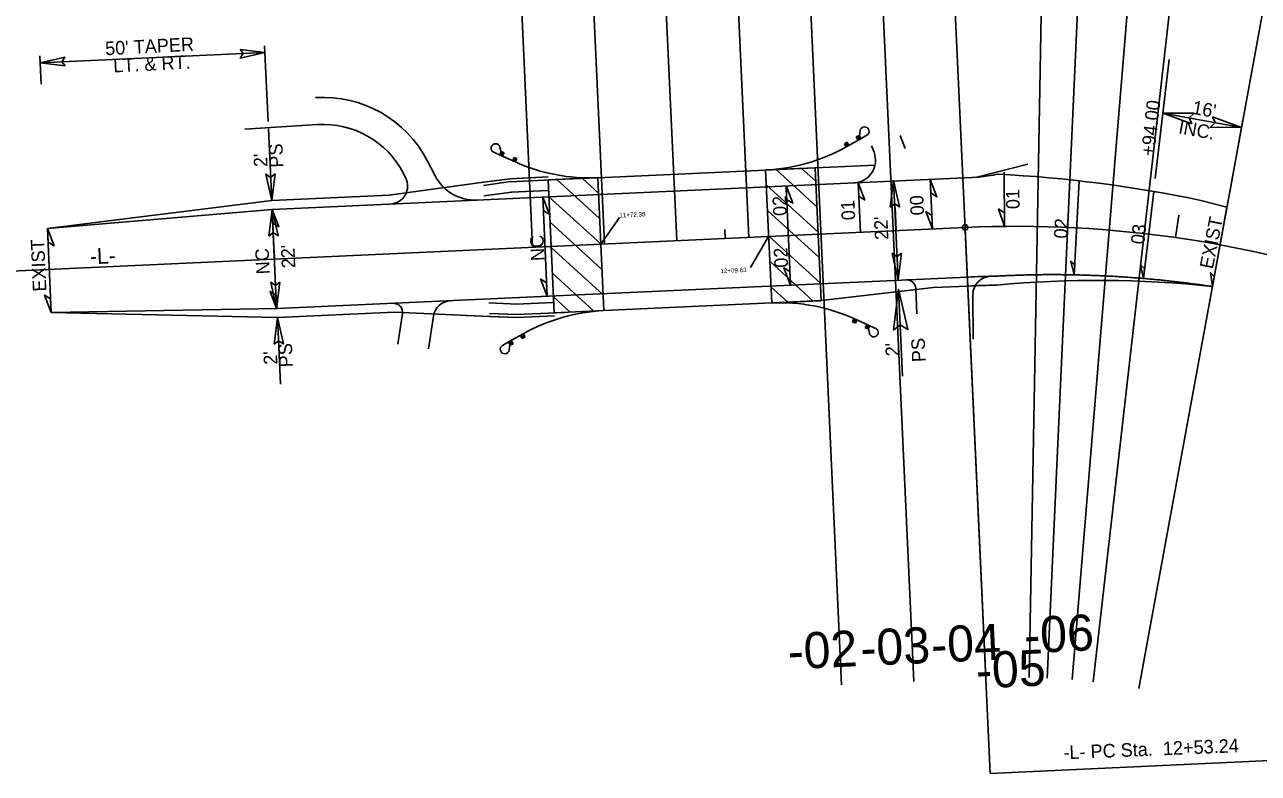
# Model space of a CAD drawing. Extents: x 1191189 to 1191812, y 892693 to 893370.
# Drawn here: x 1191327.5 to 1191601, y 892960.5 to 893126.5 of the extents above; entities that cross this region are included whole.
import ezdxf

# ---------------------------------------------------------------- set-up
doc = ezdxf.new("R2010")
doc.units = 0
for name, color, linetype in [('Prop Approach Slab', 7, 'Continuous'), ('Prop DSN Text', 7, 'Continuous'), ('Prop EOT', 7, 'Continuous'), ('Prop Guardrail Anchor Unit CELL', 7, 'Continuous'), ('Prop Guardrail Shop Curved', 7, 'Continuous'), ('Prop Horizontal Alignment', 7, 'Continuous'), ('Prop Horizontal Alignment Station Label', 7, 'Continuous'), ('Prop Horizontal Alignment Tick Small', 7, 'Continuous'), ('Prop Leader Line Medium', 7, 'Continuous'), ('Prop Paved Shoulder', 7, 'Continuous'), ('Prop Roadway Bridge', 7, 'Continuous'), ('Prop Superelevation  Arrow CELL', 7, 'Continuous'), ('Prop Superelevation Label', 7, 'Continuous'), ('Prop Terminator CELL', 7, 'Continuous'), ('Scratch_Level_0', 7, 'Continuous'), ('Scratch_Level_1', 7, 'Continuous'), ('Scratch_Level_5', 7, 'Continuous'), ('Scratch_Level_8', 7, 'Continuous'), ('Scratch_Level_9', 7, 'Continuous'), ('Sheet Data Field CELL', 7, 'Continuous'), ('Sheet PE Seal Cell', 7, 'Continuous'), ('Sheet Plot Border Inside CELL', 7, 'Continuous')]:
    doc.layers.add(name, color=color, linetype=linetype)

msp = doc.modelspace()

# ---------------------------------------------------------------- linework, layer by layer
at = {"layer": 'Prop Approach Slab'}
for p, q in [((1191491.73, 893094.26), (1191502.72, 893094.77)), ((1191503.11, 893086.13), (1191494.09, 893094.37)), ((1191502.86, 893091.76), (1191499.71, 893094.63)), ((1191502.72, 893094.77), (1191504.07, 893065.3)), ((1191443.53, 893092.06), (1191454.52, 893092.56)), ((1191443.53, 893092.06), (1191444.88, 893062.59)), ((1191454.93, 893083.51), (1191445.47, 893092.15)), ((1191454.67, 893089.16), (1191451.12, 893092.41)), ((1191503.37, 893080.48), (1191491.88, 893090.97)), ((1191455.19, 893077.86), (1191443.7, 893088.35)), ((1191503.63, 893074.83), (1191492.14, 893085.32)), ((1191455.45, 893072.21), (1191443.96, 893082.7)), ((1191455.71, 893066.56), (1191444.22, 893077.05)), ((1191503.89, 893069.18), (1191492.4, 893079.67)), ((1191502.3, 893065.22), (1191492.66, 893074.02)), ((1191453.69, 893062.99), (1191444.48, 893071.4)), ((1191448.41, 893062.75), (1191444.72, 893066.12)), ((1191496.65, 893064.96), (1191492.91, 893068.37)), ((1191493.08, 893064.79), (1191504.07, 893065.3)), ((1191444.88, 893062.59), (1191455.87, 893063.09))]:
    msp.add_line(p, q, dxfattribs=at)
at = {"layer": 'Prop DSN Text'}
for p, q in [((1191380.68, 893121.82), (1191381.45, 893105.05)), ((1191330.85, 893119.54), (1191331.12, 893113.3)), ((1191330.93, 893118.03), (1191380.75, 893120.3)), ((1191581.22, 893118.77), (1191578.11, 893092.39)), ((1191579.82, 893106.89), (1191597.25, 893103.7)), ((1191594.62, 893089.37), (1191597.55, 893105.35)), ((1191382.25, 893087.5), (1191381.52, 893103.37)), ((1191521.13, 893069.95), (1191520.12, 893091.92)), ((1191383.34, 893063.53), (1191382.34, 893085.51)), ((1191522.11, 893048.59), (1191521.23, 893067.83)), ((1191384.21, 893046.76), (1191383.54, 893061.53))]:
    msp.add_line(p, q, dxfattribs=at)
at = {"layer": 'Prop EOT'}
for p, q in [((1191376.26, 893103.29), (1191392.37, 893104.32)), ((1191522.69, 893099.01), (1191521.58, 893101.9)), ((1191515.77, 893098.19), (1191515.23, 893099.6)), ((1191418.45, 893093), (1191416.77, 893096.25)), ((1191411.44, 893093.51), (1191411.94, 893092.53)), ((1191549.85, 893095.56), (1191538.57, 893092.64)), ((1191382.34, 893085.51), (1191537.42, 893092.6)), ((1191537.42, 893092.6), (1191538.92, 893092.7)), ((1191382.34, 893085.51), (1191332.53, 893081.3)), ((1191587.94, 893087.59), (1191594.01, 893086.02)), ((1191383.44, 893063.53), (1191536.47, 893070.53)), ((1191525.28, 893062.4), (1191525.01, 893068.01)), ((1191537.77, 893056.75), (1191537.71, 893066.69)), ((1191383.44, 893063.53), (1191333.38, 893062.68)), ((1191410.21, 893055.62), (1191411.21, 893062.42)), ((1191417.02, 893054.61), (1191418.1, 893061.88))]:
    msp.add_line(p, q, dxfattribs=at)
for centre, radius, start, end in [((1191393.65, 893084.36), 26, 27.2195, 93.6699), ((1191393.65, 893084.36), 20, 27.2195, 93.6699), ((1191511.1, 893096.4), 5, 272.6195, 20.9612), ((1191408.38, 893090.7), 4, 272.6195, 27.2195), ((1191427.34, 893097.57), 10, 207.2195, 272.6195), ((1191535.25, 893131.59), 39.06, 275.3979, 281.7955), ((1191527.61, 892795.99), 297.77, 78.311, 86.9917), ((1191523.01, 893067.92), 2, 2.7886, 92.6195), ((1191547.39, 892831.78), 239, 91.07, 92.6195), ((1191541.71, 893066.71), 4, 91.3868, 180.3716), ((1191409.24, 893062.71), 2, 351.5848, 92.6195), ((1191422.06, 893061.29), 4, 92.6195, 171.5848)]:
    msp.add_arc(centre, radius, start, end, dxfattribs=at)
msp.add_spline([(1191542.93, 893070.74), (1191543.58, 893070.77), (1191544.22, 893070.81), (1191544.87, 893070.83), (1191545.51, 893070.86), (1191546.16, 893070.89), (1191546.81, 893070.91), (1191547.45, 893070.93), (1191548.1, 893070.95), (1191548.74, 893070.97), (1191549.39, 893070.99), (1191550.04, 893071.01), (1191550.68, 893071.02), (1191551.33, 893071.03), (1191551.98, 893071.04), (1191552.63, 893071.05), (1191553.27, 893071.06), (1191553.92, 893071.06), (1191554.57, 893071.06), (1191555.22, 893071.06), (1191555.86, 893071.06), (1191556.51, 893071.06), (1191557.16, 893071.06), (1191557.81, 893071.05), (1191558.45, 893071.04), (1191559.1, 893071.04), (1191559.75, 893071.02), (1191560.4, 893071.01), (1191561.04, 893071), (1191561.69, 893070.98), (1191562.34, 893070.96), (1191562.99, 893070.94), (1191563.63, 893070.92), (1191564.28, 893070.9), (1191564.93, 893070.87), (1191565.58, 893070.85), (1191566.23, 893070.82), (1191566.87, 893070.79), (1191567.52, 893070.75), (1191568.17, 893070.72), (1191568.82, 893070.69), (1191569.46, 893070.65), (1191570.11, 893070.61), (1191570.76, 893070.57), (1191571.41, 893070.53), (1191572.05, 893070.48), (1191572.7, 893070.44), (1191573.35, 893070.39), (1191574, 893070.34), (1191574.64, 893070.29), (1191575.29, 893070.23), (1191575.94, 893070.18), (1191576.58, 893070.12), (1191577.23, 893070.06), (1191577.88, 893070), (1191578.52, 893069.94), (1191579.17, 893069.88), (1191579.82, 893069.81), (1191580.46, 893069.74), (1191581.11, 893069.68), (1191581.75, 893069.61), (1191582.4, 893069.53), (1191583.05, 893069.46), (1191583.69, 893069.38), (1191584.34, 893069.3), (1191584.98, 893069.23), (1191585.63, 893069.14), (1191586.27, 893069.06), (1191586.92, 893068.98), (1191587.56, 893068.89), (1191588.2, 893068.8), (1191588.85, 893068.71), (1191589.49, 893068.62), (1191590.78, 893068.46)], degree=3, dxfattribs=at)
at = {"layer": 'Prop Guardrail Anchor Unit CELL'}
for p, q in [((1191512.45, 893101.93), (1191511.84, 893101.58)), ((1191511.84, 893101.58), (1191512.24, 893100.88)), ((1191512.85, 893101.22), (1191511.84, 893101.58)), ((1191512.24, 893100.88), (1191512.45, 893101.93)), ((1191512.85, 893101.22), (1191512.45, 893101.93)), ((1191512.7, 893102.96), (1191512.55, 893101.76)), ((1191512.68, 893101.13), (1191514.17, 893101.97)), ((1191432.84, 893099.32), (1191433.08, 893098.25)), ((1191509.8, 893100.44), (1191509.19, 893100.09)), ((1191509.19, 893100.09), (1191509.59, 893099.39)), ((1191510.2, 893099.73), (1191509.19, 893100.09)), ((1191509.59, 893099.39), (1191512.68, 893101.13)), ((1191509.59, 893099.39), (1191509.8, 893100.44)), ((1191509.59, 893099.39), (1191510.2, 893099.73)), ((1191510.2, 893099.73), (1191509.8, 893100.44)), ((1191512.24, 893100.88), (1191512.85, 893101.22)), ((1191512.73, 893101.16), (1191512.62, 893101.09)), ((1191512.73, 893101.16), (1191512.62, 893101.09)), ((1191512.85, 893101.22), (1191512.68, 893101.53)), ((1191512.85, 893101.22), (1191512.68, 893101.53)), ((1191433.04, 893097.49), (1191431.47, 893098.2)), ((1191432.79, 893097.6), (1191433.12, 893098.34)), ((1191432.79, 893097.6), (1191433.76, 893098.05)), ((1191432.79, 893097.6), (1191432.94, 893097.92)), ((1191432.79, 893097.6), (1191432.94, 893097.92)), ((1191433.43, 893097.32), (1191432.79, 893097.6)), ((1191432.91, 893097.55), (1191433.04, 893097.49)), ((1191432.91, 893097.55), (1191433.04, 893097.49)), ((1191436.27, 893096.05), (1191433.04, 893097.49)), ((1191433.12, 893098.34), (1191433.76, 893098.05)), ((1191433.43, 893097.32), (1191433.12, 893098.34)), ((1191433.76, 893098.05), (1191433.43, 893097.32)), ((1191435.63, 893096.33), (1191435.96, 893097.07)), ((1191435.63, 893096.33), (1191436.6, 893096.78)), ((1191436.27, 893096.05), (1191435.63, 893096.33)), ((1191435.96, 893097.07), (1191436.6, 893096.78)), ((1191436.27, 893096.05), (1191435.96, 893097.07)), ((1191436.6, 893096.78), (1191436.27, 893096.05)), ((1191332.94, 893072.23), (1191332.94, 893072.23)), ((1191511, 893060.57), (1191511.33, 893061.31)), ((1191511.97, 893061.02), (1191511, 893060.57)), ((1191511.64, 893060.29), (1191511, 893060.57)), ((1191511.33, 893061.31), (1191514.56, 893059.86)), ((1191511.33, 893061.31), (1191511.97, 893061.02)), ((1191511.33, 893061.31), (1191511.64, 893060.29)), ((1191511.97, 893061.02), (1191511.64, 893060.29)), ((1191438.01, 893057.95), (1191434.92, 893056.22)), ((1191438.01, 893057.95), (1191437.4, 893057.61)), ((1191438.01, 893057.95), (1191437.8, 893056.91)), ((1191438.41, 893057.25), (1191438.01, 893057.95)), ((1191513.84, 893059.3), (1191514.17, 893060.04)), ((1191514.81, 893059.75), (1191513.84, 893059.3)), ((1191514.48, 893059.02), (1191513.84, 893059.3)), ((1191514.17, 893060.04), (1191514.81, 893059.75)), ((1191514.17, 893060.04), (1191514.48, 893059.02)), ((1191514.81, 893059.75), (1191514.48, 893059.02)), ((1191514.76, 893058.04), (1191514.52, 893059.11)), ((1191514.68, 893059.81), (1191514.56, 893059.86)), ((1191514.56, 893059.86), (1191516.13, 893059.16)), ((1191514.68, 893059.81), (1191514.56, 893059.86)), ((1191514.81, 893059.75), (1191514.66, 893059.43)), ((1191514.81, 893059.75), (1191514.66, 893059.43)), ((1191434.92, 893056.22), (1191433.42, 893055.38)), ((1191435.36, 893056.46), (1191434.75, 893056.12)), ((1191434.75, 893056.12), (1191434.92, 893055.81)), ((1191434.75, 893056.12), (1191434.92, 893055.81)), ((1191434.75, 893056.12), (1191435.14, 893055.42)), ((1191434.75, 893056.12), (1191435.75, 893055.76)), ((1191434.86, 893056.19), (1191434.98, 893056.25)), ((1191434.86, 893056.19), (1191434.98, 893056.25)), ((1191434.89, 893054.39), (1191435.05, 893055.58)), ((1191435.36, 893056.46), (1191435.14, 893055.42)), ((1191435.14, 893055.42), (1191435.75, 893055.76)), ((1191435.75, 893055.76), (1191435.36, 893056.46)), ((1191437.4, 893057.61), (1191437.8, 893056.91)), ((1191437.4, 893057.61), (1191438.41, 893057.25)), ((1191437.8, 893056.91), (1191438.41, 893057.25))]:
    msp.add_line(p, q, dxfattribs=at)
for centre, major_axis, start_param, end_param in [((1191513.69, 893102.83), (-0.486, 0.866), 3.141593, 7.214552), ((1191431.87, 893099.1), (-0.406, -0.906), 2.210226, 6.283185), ((1191515.73, 893058.25), (0.406, 0.906), 2.210226, 6.283185), ((1191433.91, 893054.51), (0.487, -0.866), 3.141593, 7.214552)]:
    msp.add_ellipse(centre, major_axis=major_axis, ratio=0.995379, start_param=start_param, end_param=end_param, dxfattribs=at)
at = {"layer": 'Prop Guardrail Shop Curved'}
for centre, start, end in [((1191489.9, 893134.21), 272.6195, 299.4769), ((1191452.69, 893132.52), 245.7621, 272.6195), ((1191494.91, 893024.84), 65.7587, 92.6195), ((1191457.7, 893023.13), 92.6195, 119.4802)]:
    msp.add_arc(centre, 40, start, end, dxfattribs=at)
at = {"layer": 'Prop Horizontal Alignment'}
msp.add_line((1191282.99, 893069.95), (1191535.97, 893081.52), dxfattribs=at)
msp.add_arc((1191547.39, 892831.78), 250, 70.2703, 92.6195, dxfattribs=at)
at = {"layer": 'Prop Horizontal Alignment Station Label'}
for p, q in [((1191536, 893080.92), (1191541.5, 892960.51)), ((1191541.5, 892960.51), (1191605.25, 892963.43))]:
    msp.add_line(p, q, dxfattribs=at)
msp.add_circle((1191535.97, 893081.52), 0.6, dxfattribs=at)
at = {"layer": 'Prop Horizontal Alignment Tick Small'}
for p, q in [((1191520.67, 893080.94), (1191520.44, 893085.93)), ((1191582.61, 893079.29), (1191583.31, 893084.24)), ((1191482.78, 893079.09), (1191482.69, 893081.09)), ((1191582.61, 893079.29), (1191582.89, 893081.27)), ((1191382.89, 893074.52), (1191382.8, 893076.52))]:
    msp.add_line(p, q, dxfattribs=at)
at = {"layer": 'Prop Paved Shoulder'}
for p, q in [((1191502.72, 893094.77), (1191516, 893095.37)), ((1191429.16, 893091.53), (1191408.27, 893088.69)), ((1191429.16, 893091.53), (1191435.09, 893092.34)), ((1191435.09, 893092.34), (1191443.5, 893092.72)), ((1191382.25, 893087.5), (1191408.27, 893088.69)), ((1191382.25, 893087.5), (1191332.53, 893081.3)), ((1191504.07, 893065.3), (1191528.96, 893068.19)), ((1191528.96, 893068.19), (1191536.56, 893068.54)), ((1191383.54, 893061.53), (1191333.38, 893062.68)), ((1191383.54, 893061.53), (1191409.46, 893062.72)), ((1191430.52, 893061.8), (1191409.46, 893062.72)), ((1191430.52, 893061.8), (1191436.54, 893061.54)), ((1191436.54, 893061.54), (1191444.91, 893061.92))]:
    msp.add_line(p, q, dxfattribs=at)
for centre, radius, start, end in [((1191565.46, 892831.69), 238.11, 83.8943, 95.4198), ((1191547.32, 892834.08), 234.71, 91.0624, 92.627)]:
    msp.add_arc(centre, radius, start, end, dxfattribs=at)
at = {"layer": 'Prop Roadway Bridge'}
for p, q in [((1191454.52, 893092.56), (1191491.73, 893094.26)), ((1191491.73, 893094.26), (1191493.08, 893064.79)), ((1191454.52, 893092.56), (1191455.87, 893063.09)), ((1191455.87, 893063.09), (1191493.08, 893064.79))]:
    msp.add_line(p, q, dxfattribs=at)
at = {"layer": 'Prop Superelevation  Arrow CELL'}
for p, q in [((1191544.72, 893081.77), (1191544.6, 893093.77)), ((1191497.27, 893068.74), (1191496.27, 893090.72)), ((1191512.25, 893091.45), (1191512.75, 893080.46)), ((1191528.74, 893081.19), (1191528.23, 893092.18)), ((1191560.16, 893071.02), (1191561.27, 893091.85)), ((1191443.33, 893066.27), (1191442.32, 893088.25)), ((1191577.77, 893089.51), (1191575.5, 893070.22)), ((1191590.78, 893068.46), (1191594.01, 893086.02)), ((1191382.36, 893084.97), (1191382.85, 893074.29)), ((1191383.34, 893063.53), (1191382.36, 893084.97)), ((1191333.38, 893062.68), (1191332.53, 893081.3))]:
    msp.add_line(p, q, dxfattribs=at)
for points in [[(1191496.27, 893090.72), (1191497.74, 893086.88), (1191496.4, 893087.71)], [(1191512.25, 893091.45), (1191513.73, 893087.61), (1191512.39, 893088.45)], [(1191528.23, 893092.18), (1191529.71, 893088.34), (1191528.37, 893089.18)], [(1191442.32, 893088.25), (1191443.8, 893084.41), (1191442.46, 893085.25)], [(1191382.34, 893085.51), (1191383.82, 893081.67), (1191382.48, 893082.5)], [(1191544.72, 893081.77), (1191543.38, 893085.65), (1191544.69, 893084.78)], [(1191528.74, 893081.19), (1191527.26, 893085.03), (1191528.6, 893084.19)], [(1191332.53, 893081.3), (1191334, 893077.46), (1191332.66, 893078.3)], [(1191497.27, 893068.74), (1191495.8, 893072.58), (1191497.13, 893071.74)], [(1191560.16, 893071.02), (1191559.37, 893074), (1191560.3, 893073.27)], [(1191575.5, 893070.22), (1191574.87, 893073.23), (1191575.76, 893072.45)], [(1191590.78, 893068.46), (1191590.35, 893071.51), (1191591.19, 893070.67)], [(1191443.33, 893066.27), (1191441.85, 893070.11), (1191443.19, 893069.28)], [(1191333.38, 893062.68), (1191331.9, 893066.52), (1191333.24, 893065.68)], [(1191383.34, 893063.53), (1191381.87, 893067.36), (1191383.21, 893066.53)]]:
    msp.add_lwpolyline(points, close=True, dxfattribs=at)
at = {"layer": 'Prop Terminator CELL'}
for points in [[(1191375.23, 893121), (1191380.75, 893120.3), (1191375.28, 893119.08), (1191375.94, 893120.08)], [(1191336.45, 893117.33), (1191330.93, 893118.03), (1191336.39, 893119.25), (1191335.74, 893118.25)], [(1191586.25, 893104.53), (1191579.82, 893106.89), (1191586.71, 893106.85), (1191585.65, 893105.82)], [(1191590.82, 893106.06), (1191597.25, 893103.7), (1191590.35, 893103.74), (1191591.42, 893104.77)], [(1191382.99, 893093.39), (1191382.25, 893087.5), (1191380.94, 893093.33), (1191382.01, 893092.63)], [(1191519.38, 893086.03), (1191520.12, 893091.92), (1191521.43, 893086.09), (1191520.36, 893086.79)], [(1191381.6, 893079.62), (1191382.34, 893085.51), (1191383.65, 893079.68), (1191382.57, 893080.38)], [(1191521.87, 893075.84), (1191521.13, 893069.95), (1191519.82, 893075.78), (1191520.89, 893075.08)], [(1191384.08, 893069.42), (1191383.34, 893063.53), (1191382.04, 893069.36), (1191383.11, 893068.66)], [(1191520.09, 893058.77), (1191521.23, 893067.83), (1191523.24, 893058.87), (1191521.59, 893059.94)], [(1191382.8, 893055.64), (1191383.54, 893061.53), (1191384.85, 893055.71), (1191383.77, 893056.41)]]:
    msp.add_lwpolyline(points, close=True, dxfattribs=at)
at = {"layer": 'Scratch_Level_0'}
msp.add_line((1191590.78, 893068.46), (1191594.01, 893086.02), dxfattribs=at)
at = {"layer": 'Scratch_Level_1'}
for p, q in [((1191531.4, 893181.42), (1191540.54, 892981.63)), ((1191531.4, 893181.42), (1191540.54, 892981.63)), ((1191553.79, 893181.72), (1191550.14, 892981.76)), ((1191563.25, 893181.42), (1191554.19, 892981.63)), ((1191467.47, 893178.49), (1191472.04, 893078.6)), ((1191483.45, 893179.22), (1191488.02, 893079.33)), ((1191499.43, 893179.96), (1191508.57, 892980.16)), ((1191515.42, 893180.69), (1191524.56, 892980.9)), ((1191576.16, 893180.6), (1191559.72, 892981.28)), ((1191586.97, 893179.54), (1191564.36, 892980.82)), ((1191435.5, 893177.03), (1191440.07, 893077.13)), ((1191451.48, 893177.76), (1191456.05, 893077.87)), ((1191610.51, 893176.05), (1191574.44, 892979.32))]:
    msp.add_line(p, q, dxfattribs=at)
at = {"layer": 'Scratch_Level_5'}
for p, q in [((1191491.73, 893094.27), (1191502.72, 893094.78)), ((1191443.53, 893092.07), (1191454.52, 893092.57)), ((1191493.08, 893064.78), (1191504.07, 893065.29)), ((1191444.88, 893062.58), (1191455.87, 893063.08))]:
    msp.add_line(p, q, dxfattribs=at)
at = {"layer": 'Scratch_Level_8'}
for points in [[(1191459.33, 893083.72), (1191455.19, 893077.83)], [(1191488.35, 893072.68), (1191492.4, 893079.53)]]:
    msp.add_lwpolyline(points, dxfattribs=at)
at = {"layer": 'Scratch_Level_9'}
for p, q in [((1191512.25, 893091.45), (1191512.75, 893080.46)), ((1191528.23, 893092.18), (1191528.74, 893081.19)), ((1191561.27, 893091.85), (1191560.16, 893071.02)), ((1191382.36, 893084.97), (1191382.85, 893074.29))]:
    msp.add_line(p, q, dxfattribs=at)
at = {"layer": 'Sheet Data Field CELL'}
for p, q in [((1191429.3, 893088.53), (1191435.46, 893089.36)), ((1191435.27, 893089.34), (1191443.64, 893089.73)), ((1191436.67, 893064.54), (1191430.38, 893064.81)), ((1191436.4, 893064.54), (1191444.77, 893064.92))]:
    msp.add_line(p, q, dxfattribs=at)
at = {"layer": 'Sheet PE Seal Cell'}
for p, q in [((1191429.19, 893090.86), (1191435.18, 893091.68)), ((1191435.14, 893091.67), (1191445.78, 893092.16)), ((1191436.54, 893062.21), (1191430.49, 893062.47)), ((1191436.54, 893062.21), (1191447.13, 893062.69))]:
    msp.add_line(p, q, dxfattribs=at)
at = {"layer": 'Sheet Plot Border Inside CELL'}
for p, q in [((1191429.16, 893091.53), (1191435.09, 893092.34)), ((1191435.09, 893092.34), (1191440.96, 893092.61)), ((1191436.54, 893061.54), (1191425.17, 893062.04)), ((1191436.54, 893061.54), (1191444.91, 893061.92)), ((1191436.54, 893061.54), (1191444.91, 893061.92))]:
    msp.add_line(p, q, dxfattribs=at)

# ---------------------------------------------------------------- texts
at = {"layer": 'Prop DSN Text'}
for s, rotation, p in [("50' TAPER ", 2.9229, (1191345.39, 893119.7)), ('LT. & RT.', 2.9229, (1191347.18, 893115.88)), ('+94.00', 83.5811, (1191577.88, 893097.26)), ("16'", 349.6108, (1191586.15, 893106.74)), ('INC.', 349.6108, (1191583.11, 893102.4)), ('PS', 92.4915, (1191384.83, 893094.85)), ("2'", 92.4915, (1191381.33, 893094.99)), ("22'", 92.4915, (1191518.97, 893078.83)), ("22'", 92.4915, (1191387.49, 893072.55)), ('PS', 92.4915, (1191386.94, 893050.59)), ("2'", 92.4915, (1191521.39, 893053.04)), ('PS', 92.4915, (1191527.22, 893051.74)), ("2'", 92.4915, (1191383.52, 893051.16))]:
    msp.add_text(s, height=3, rotation=rotation, dxfattribs=at).set_placement(p)
at = {"layer": 'Prop Horizontal Alignment Station Label'}
msp.add_text('-L- PC Sta.  12+53.24', height=3, rotation=2.3154, dxfattribs=at).set_placement((1191557.81, 892963.62))
at = {"layer": 'Prop Leader Line Medium'}
msp.add_text('-L- ', height=3.5, rotation=2.2753, dxfattribs=at).set_placement((1191342.01, 893073.37))
at = {"layer": 'Prop Superelevation Label'}
for s, rotation, p in [('02', 92.6195, (1191496.44, 893084.14)), ('00', 92.6195, (1191526.88, 893084.28)), ('01', 91.2991, (1191548.08, 893085.62)), ('01', 92.6195, (1191511.61, 893083.2)), ('02', 86.2228, (1191558.61, 893078.98)), ('EXIST', 78.7968, (1191590.87, 893072.18)), ('NC', 92.6195, (1191442.74, 893074.15)), ('03', 83.8593, (1191575.66, 893077.67)), ('EXIST', 92.4915, (1191332.31, 893067.38)), ('NC', 92.6195, (1191381.83, 893071.2)), ('02', 92.6195, (1191496.72, 893072.67))]:
    msp.add_text(s, height=3, rotation=rotation, dxfattribs=at).set_placement(p)
at = {"layer": 'Scratch_Level_1'}
for s, p in [('-06', (1191549.22, 892987.1)), ('-02', (1191496.79, 892983.55)), ('-03', (1191512.91, 892984.29)), ('-04', (1191528.6, 892985)), ('-05', (1191538.53, 892979.3))]:
    msp.add_text(s, height=8, rotation=2.6614, dxfattribs=at).set_placement(p)
at = {"layer": 'Scratch_Level_8'}
for s, p in [('11+72.38', (1191459.33, 893083.72)), ('12+09.63', (1191481.74, 893071.38))]:
    msp.add_text(s, height=1, rotation=2.6195, dxfattribs=at).set_placement(p)

doc.saveas('drawing.dxf')
